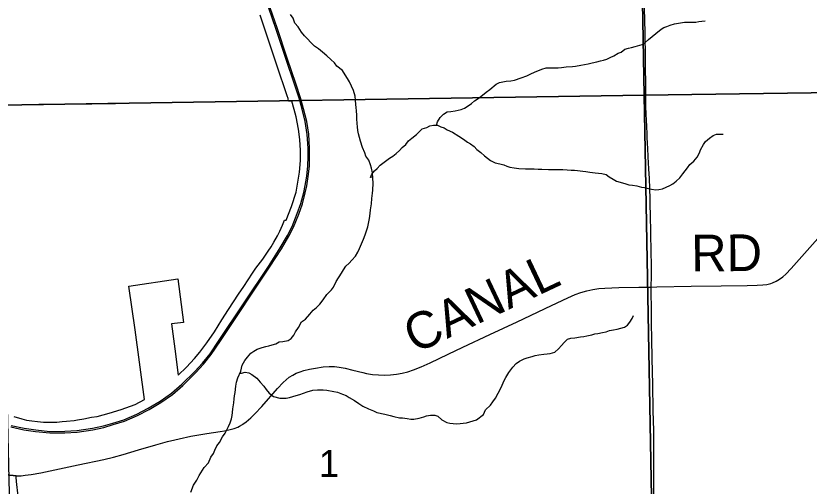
# Model space of a CAD drawing. Extents: x 0 to 34, y 0 to 22.
# Drawn here: x 22.282 to 23.511, y 14.057 to 14.786 of the extents above; entities that cross this region are included whole.
import ezdxf

# ---------------------------------------------------------------- set-up
doc = ezdxf.new("R2010")
doc.units = 0
for name, color, linetype in [('GM_X_City_Street', 7, 'Continuous'), ('GM_X_Corporation', 7, 'Continuous'), ('GM_X_County_Road', 7, 'Continuous'), ('GM_X_County_Road_Text', 7, 'Continuous'), ('GM_X_Minor_River', 7, 'Continuous'), ('GM_X_Rail_Line', 7, 'Continuous'), ('GM_X_Section', 7, 'Continuous'), ('GM_X_Section_Text', 7, 'Continuous'), ('GM_X_Township_Road', 7, 'Continuous')]:
    doc.layers.add(name, color=color, linetype=linetype)

msp = doc.modelspace()

# ---------------------------------------------------------------- linework, layer by layer
at = {"layer": 'GM_X_City_Street'}
msp.add_lwpolyline([(22.26, 14.6472), (22.2903, 14.648), (22.3156, 14.6486), (22.3178, 14.6487), (22.3997, 14.6493), (22.4366, 14.65)], dxfattribs=at)
at = {"layer": 'GM_X_Corporation'}
msp.add_lwpolyline([(22.2788, 14.1648), (22.2916, 14.1611), (22.2988, 14.1594), (22.3071, 14.1583), (22.3156, 14.1571), (22.3251, 14.1564), (22.3363, 14.1562), (22.3456, 14.1563), (22.354, 14.1571), (22.3606, 14.1578), (22.3724, 14.159), (22.3774, 14.1598), (22.3876, 14.1611), (22.3992, 14.1637), (22.4082, 14.1649), (22.4268, 14.17), (22.4452, 14.1759), (22.4667, 14.1836), (22.4815, 14.1915), (22.467, 14.2995), (22.4571, 14.3667), (22.5328, 14.3785), (22.5418, 14.3104), (22.5231, 14.3083), (22.5283, 14.27), (22.5338, 14.2291), (22.5467, 14.2416), (22.5587, 14.2547), (22.5672, 14.2647), (22.5777, 14.2791), (22.5897, 14.2964), (22.6011, 14.3147), (22.6115, 14.3309), (22.6269, 14.3543), (22.6353, 14.3665), (22.6489, 14.3869), (22.6537, 14.3946), (22.6649, 14.409), (22.6732, 14.4212), (22.6775, 14.4277), (22.6819, 14.4351), (22.6873, 14.4449), (22.6911, 14.4523), (22.6952, 14.4614), (22.6983, 14.4691), (22.7006, 14.4691), (22.7091, 14.4902), (22.7161, 14.5127), (22.7215, 14.5438), (22.7229, 14.5617), (22.7229, 14.5771), (22.7219, 14.5941), (22.7199, 14.61), (22.7161, 14.6295), (22.7133, 14.6409), (22.7096, 14.6537), (22.7046, 14.6538), (22.704, 14.6577), (22.7025, 14.6618), (22.6865, 14.7092), (22.6603, 14.7871)], dxfattribs=at)
at = {"layer": 'GM_X_County_Road'}
for points in [[(23.2664, 14.3656), (23.275, 14.3658), (23.3279, 14.367), (23.3744, 14.3676), (23.4147, 14.3681), (23.4302, 14.3683), (23.4394, 14.3689), (23.4455, 14.3697), (23.4514, 14.3711), (23.4543, 14.3721), (23.4599, 14.3745), (23.4652, 14.3776), (23.4702, 14.3812), (23.4747, 14.3853), (23.4831, 14.3943), (23.5283, 14.4456)], [(22.6331, 14.1526), (22.6339, 14.1531), (22.6389, 14.1567), (22.6459, 14.1628), (22.6524, 14.1693), (22.6629, 14.1807), (22.6875, 14.2086), (22.696, 14.2177), (22.7006, 14.2219), (22.7056, 14.2258), (22.7109, 14.2291), (22.7165, 14.232), (22.7223, 14.2343), (22.7283, 14.2362), (22.7372, 14.2383), (22.7461, 14.2401), (22.7582, 14.2417), (22.7675, 14.2424), (22.7758, 14.2423), (22.783, 14.2415), (22.7921, 14.2397), (22.8043, 14.2366), (22.8194, 14.2329), (22.8254, 14.2316), (22.8346, 14.2302), (22.8438, 14.2293), (22.853, 14.229), (22.8623, 14.2294), (22.8715, 14.2303), (22.8806, 14.2319), (22.8895, 14.2341), (22.8983, 14.2371), (22.9097, 14.2417), (22.9239, 14.248), (22.9518, 14.2615), (22.9743, 14.2722), (23.0164, 14.292), (23.0586, 14.3117), (23.112, 14.3369), (23.1372, 14.3489), (23.1487, 14.3538), (23.1575, 14.357), (23.1665, 14.3597), (23.1756, 14.3617), (23.1849, 14.3631), (23.1942, 14.3639), (23.216, 14.3647), (23.247, 14.3654), (23.2664, 14.3656)], [(22.5984, 14.1418), (22.6053, 14.1429), (22.6143, 14.1448), (22.6203, 14.1464), (22.626, 14.1486), (22.6287, 14.1499), (22.6331, 14.1526)], [(22.5282, 14.129), (22.5349, 14.1306), (22.5532, 14.1343), (22.5777, 14.1385), (22.5984, 14.1418)], [(22.2824, 14.0728), (22.2904, 14.0732), (22.2966, 14.0739), (22.3058, 14.0752), (22.321, 14.0779), (22.3788, 14.0899), (22.4183, 14.0984), (22.4334, 14.1019), (22.4484, 14.1059), (22.472, 14.1131), (22.4988, 14.1213), (22.5168, 14.1262), (22.5282, 14.129)], [(22.2159, 14.0893), (22.2266, 14.0863), (22.2358, 14.0837), (22.2507, 14.0795), (22.2629, 14.0764), (22.2719, 14.0743), (22.2778, 14.0733), (22.2824, 14.0728)]]:
    msp.add_lwpolyline(points, dxfattribs=at)
at = {"layer": 'GM_X_Minor_River'}
for points in [[(22.8027, 14.407), (22.8083, 14.4132), (22.812, 14.4197), (22.8146, 14.4254), (22.8205, 14.4399), (22.8231, 14.4464), (22.8257, 14.4544), (22.8275, 14.459), (22.8282, 14.464), (22.83, 14.4716), (22.831, 14.4796), (22.8317, 14.4853), (22.8331, 14.4944), (22.8334, 14.5028), (22.8344, 14.5111), (22.8351, 14.5157), (22.8358, 14.5263), (22.8353, 14.5343), (22.8344, 14.5427), (22.8332, 14.5499), (22.8312, 14.5548), (22.8288, 14.562), (22.8242, 14.5684), (22.8226, 14.5737), (22.8191, 14.582), (22.8159, 14.5914), (22.8131, 14.6032), (22.8119, 14.6081), (22.8111, 14.6138), (22.811, 14.6191), (22.8105, 14.6263), (22.8101, 14.632), (22.8096, 14.6384), (22.8092, 14.6437), (22.8087, 14.6483), (22.8082, 14.6551), (22.8078, 14.6612), (22.805, 14.6699), (22.7991, 14.6835), (22.796, 14.6888), (22.7921, 14.6944), (22.7879, 14.7012), (22.7794, 14.7079), (22.7755, 14.7128), (22.7698, 14.7184), (22.7636, 14.7237), (22.7571, 14.7293), (22.7509, 14.7345), (22.7448, 14.739), (22.7398, 14.7439), (22.7336, 14.7506), (22.729, 14.7547), (22.7247, 14.7604), (22.7193, 14.769), (22.7143, 14.7743), (22.7115, 14.7822), (22.7073, 14.7879)], [(22.9339, 14.6165), (22.9353, 14.6215), (22.9394, 14.6284), (22.9443, 14.6334), (22.95, 14.6369), (22.9557, 14.6377), (22.9625, 14.6386), (22.9674, 14.6394), (22.972, 14.6406), (22.9773, 14.6426), (22.9829, 14.6464), (22.9878, 14.6499), (22.9927, 14.6542), (22.998, 14.6577), (23.0048, 14.6627), (23.0104, 14.6673), (23.0161, 14.6719), (23.0262, 14.6801), (23.0315, 14.6824), (23.0364, 14.6836), (23.0418, 14.6844), (23.049, 14.6853), (23.0547, 14.6861), (23.0649, 14.6897), (23.0736, 14.6928), (23.08, 14.696), (23.0857, 14.6983), (23.0967, 14.7034), (23.1035, 14.705), (23.1088, 14.7055), (23.1141, 14.7055), (23.1221, 14.7053), (23.1274, 14.7057), (23.1347, 14.7066), (23.1442, 14.7075), (23.1491, 14.7079), (23.1574, 14.7095), (23.1684, 14.7116), (23.1749, 14.7128), (23.1821, 14.7144), (23.1878, 14.716), (23.1923, 14.7172), (23.1973, 14.7188), (23.2025, 14.7212), (23.2082, 14.7239), (23.215, 14.7278), (23.2196, 14.7297), (23.2256, 14.734), (23.2313, 14.7356), (23.2358, 14.7368), (23.2415, 14.7384), (23.2521, 14.7416), (23.257, 14.7443), (23.2619, 14.7489), (23.2679, 14.7539), (23.2732, 14.7582), (23.2815, 14.7651), (23.286, 14.7678), (23.2905, 14.7694), (23.2955, 14.7714), (23.3023, 14.7734), (23.3114, 14.775), (23.3178, 14.7759), (23.3353, 14.7761), (23.3399, 14.7769), (23.3448, 14.7774), (23.3498, 14.7782)], [(22.8351, 14.5358), (22.8315, 14.5354), (22.8337, 14.5404), (22.8374, 14.5454), (22.8419, 14.5492), (22.8464, 14.5542), (22.8525, 14.5589), (22.8611, 14.5651), (22.866, 14.5682), (22.8713, 14.5724), (22.8762, 14.577), (22.8807, 14.5816), (22.8863, 14.5867), (22.8901, 14.592), (22.8957, 14.5963), (22.9025, 14.6017), (22.907, 14.6059), (22.9115, 14.6105), (22.9187, 14.6129), (22.9236, 14.6156), (22.9289, 14.6165), (22.935, 14.6166), (22.9404, 14.614), (22.9453, 14.6121), (22.9503, 14.6092), (22.9584, 14.6055), (22.9683, 14.5995), (22.9756, 14.5947), (22.9818, 14.5902), (22.9863, 14.5876), (22.9921, 14.5831), (22.9964, 14.5786), (23.0025, 14.5738), (23.0079, 14.5689), (23.0125, 14.5652), (23.0171, 14.5618), (23.0248, 14.5581), (23.032, 14.5567), (23.0381, 14.5549), (23.0427, 14.5527), (23.0473, 14.5512), (23.0542, 14.5501), (23.0614, 14.5495), (23.0717, 14.5489), (23.0781, 14.5489), (23.085, 14.5487), (23.0911, 14.5484), (23.0968, 14.5481), (23.1074, 14.5478), (23.1128, 14.5479), (23.1204, 14.5476), (23.1295, 14.5477), (23.1363, 14.5471), (23.1421, 14.5468), (23.1474, 14.5465), (23.1519, 14.5461), (23.1603, 14.5451), (23.1649, 14.5444), (23.1714, 14.5434), (23.1794, 14.5423), (23.1847, 14.542), (23.19, 14.5413), (23.1965, 14.5399), (23.2011, 14.5365), (23.2073, 14.5328), (23.2126, 14.5298), (23.2252, 14.5258), (23.2317, 14.524), (23.2371, 14.5233), (23.2439, 14.5223), (23.2512, 14.5205), (23.2561, 14.5198), (23.2618, 14.5183), (23.2668, 14.5173), (23.2733, 14.5162), (23.2782, 14.5167), (23.2835, 14.5179), (23.2949, 14.523), (23.2998, 14.5257), (23.3051, 14.5296), (23.3107, 14.5346), (23.3152, 14.5411), (23.3223, 14.5503), (23.326, 14.5553), (23.3324, 14.5607), (23.3373, 14.5668), (23.341, 14.5737), (23.3428, 14.5783), (23.3473, 14.5867), (23.3503, 14.5913), (23.3563, 14.5963), (23.362, 14.6002), (23.3673, 14.6022), (23.3726, 14.6026), (23.3775, 14.6027)], [(22.5533, 14.0478), (22.5573, 14.0585), (22.5626, 14.0661), (22.5659, 14.0734), (22.5737, 14.086), (22.5805, 14.0934), (22.5842, 14.1021), (22.5883, 14.1075), (22.5905, 14.1129), (22.5934, 14.1194), (22.5976, 14.1247), (22.6024, 14.1335), (22.6065, 14.1393), (22.6113, 14.1492), (22.6139, 14.155), (22.6161, 14.1611), (22.6172, 14.1664), (22.6179, 14.1713), (22.6182, 14.177), (22.6196, 14.1862), (22.6203, 14.1923), (22.621, 14.1968), (22.6217, 14.2022), (22.6227, 14.2117), (22.6241, 14.2181), (22.6259, 14.225), (22.6304, 14.2353), (22.6329, 14.2445), (22.6366, 14.2517), (22.6407, 14.2567), (22.646, 14.2629), (22.6509, 14.2664), (22.6558, 14.2691), (22.6637, 14.2718), (22.6694, 14.2734), (22.674, 14.2746), (22.6789, 14.2762), (22.6846, 14.2778), (22.6899, 14.2806), (22.6959, 14.2814), (22.7039, 14.2826), (22.7088, 14.2857), (22.7129, 14.2911), (22.7151, 14.2961), (22.72, 14.303), (22.7248, 14.3114), (22.7309, 14.316), (22.7376, 14.3233), (22.7425, 14.3299), (22.7477, 14.3341), (22.753, 14.3391), (22.7579, 14.3456), (22.7638, 14.3541), (22.771, 14.361), (22.774, 14.3656), (22.7784, 14.3744), (22.7866, 14.3871), (22.7896, 14.3924), (22.7933, 14.3978), (22.7982, 14.4028), (22.8027, 14.407)], [(23.2296, 14.3063), (23.2333, 14.3113), (23.2367, 14.3167), (23.2389, 14.3217)], [(22.629, 14.2323), (22.6319, 14.2323), (22.6372, 14.2339), (22.6429, 14.2324), (22.6475, 14.2302), (22.6556, 14.2243), (22.6606, 14.2182), (22.666, 14.2122), (22.6699, 14.2066), (22.6745, 14.2013), (22.6811, 14.1961), (22.691, 14.1932), (22.7009, 14.1933), (22.7058, 14.1945), (22.7111, 14.1958), (22.7164, 14.1973), (22.7221, 14.1989), (22.7278, 14.2013), (22.7331, 14.2033), (22.7422, 14.2057), (22.7494, 14.2065), (22.7581, 14.2063), (22.7639, 14.2059), (22.7745, 14.2038), (22.7802, 14.2027), (22.7883, 14.1998), (22.7936, 14.1976), (22.7986, 14.1946), (22.8067, 14.1898), (22.8136, 14.1853), (22.8197, 14.1812), (22.8281, 14.1768), (22.8362, 14.1735), (22.8411, 14.1713), (22.8537, 14.1688), (22.8617, 14.1666), (22.8674, 14.1652), (22.8762, 14.163), (22.8808, 14.1627), (22.8884, 14.1616), (22.8937, 14.161), (22.8987, 14.161), (22.9067, 14.1623), (22.9139, 14.1643), (22.9184, 14.1662), (22.9245, 14.1671), (22.9309, 14.1668), (22.9355, 14.1653), (22.9421, 14.1597), (22.9497, 14.1556), (22.9543, 14.1545), (22.9596, 14.1542), (22.965, 14.1536), (22.9703, 14.154), (22.9748, 14.1544), (22.9802, 14.1553), (22.9855, 14.1565), (22.9957, 14.1597), (23.0066, 14.1682), (23.0096, 14.1754), (23.0175, 14.1827), (23.0208, 14.1877), (23.0249, 14.1935), (23.0294, 14.2011), (23.0327, 14.2076), (23.0353, 14.2137), (23.0383, 14.2206), (23.0409, 14.2252), (23.0457, 14.2329), (23.0521, 14.2413), (23.0573, 14.2471), (23.0622, 14.2506), (23.0694, 14.2541), (23.0739, 14.2557), (23.0819, 14.258), (23.0864, 14.2596), (23.0921, 14.2605), (23.0997, 14.2613), (23.105, 14.2621), (23.11, 14.2626), (23.1168, 14.2646), (23.1228, 14.2696), (23.1273, 14.275), (23.1314, 14.2796), (23.1367, 14.285), (23.142, 14.2862), (23.1481, 14.287), (23.1568, 14.2883), (23.1617, 14.2891), (23.1663, 14.2899), (23.1743, 14.2916), (23.1788, 14.2928), (23.1834, 14.2936), (23.1906, 14.2952), (23.1963, 14.2964), (23.2019, 14.298), (23.208, 14.2992), (23.2137, 14.3004), (23.2194, 14.302), (23.2247, 14.3036), (23.2296, 14.3063)]]:
    msp.add_lwpolyline(points, dxfattribs=at)
at = {"layer": 'GM_X_Rail_Line'}
for points in [[(22.2742, 14.1489), (22.2944, 14.1444), (22.3126, 14.1418), (22.3347, 14.1396), (22.358, 14.1397), (22.377, 14.1409), (22.4013, 14.1444), (22.4184, 14.148), (22.4328, 14.1523), (22.4503, 14.1578), (22.4704, 14.1665), (22.4884, 14.1758), (22.5068, 14.1866), (22.5248, 14.1991), (22.541, 14.213), (22.5611, 14.2329), (22.5729, 14.2461), (22.5848, 14.2608), (22.5993, 14.282), (22.6752, 14.3963), (22.6937, 14.425), (22.7051, 14.4443), (22.7121, 14.4586), (22.7203, 14.4786), (22.7259, 14.4945), (22.7304, 14.5116), (22.7327, 14.5224), (22.7351, 14.5371), (22.7368, 14.553), (22.7372, 14.5673), (22.7371, 14.5809), (22.7357, 14.6023), (22.7326, 14.6223), (22.7278, 14.6417), (22.723, 14.6588), (22.7163, 14.6794), (22.7024, 14.7204), (22.6869, 14.7671), (22.6763, 14.7984)], [(22.2748, 14.1512), (22.2948, 14.1467), (22.3129, 14.1441), (22.3348, 14.1419), (22.3579, 14.1421), (22.3767, 14.1433), (22.4009, 14.1467), (22.4178, 14.1503), (22.4321, 14.1546), (22.4494, 14.16), (22.4694, 14.1686), (22.4872, 14.1778), (22.5055, 14.1886), (22.5233, 14.2009), (22.5394, 14.2148), (22.5594, 14.2345), (22.5711, 14.2477), (22.5829, 14.2622), (22.5973, 14.2833), (22.6733, 14.3976), (22.6917, 14.4262), (22.703, 14.4454), (22.71, 14.4596), (22.7181, 14.4795), (22.7237, 14.4951), (22.7281, 14.5121), (22.7304, 14.5229), (22.7327, 14.5374), (22.7345, 14.5532), (22.7348, 14.5673), (22.7347, 14.5808), (22.7333, 14.6021), (22.7303, 14.6219), (22.7255, 14.6411), (22.7208, 14.6581), (22.7141, 14.6786), (22.7002, 14.7196), (22.6847, 14.7664), (22.6741, 14.7976)]]:
    msp.add_lwpolyline(points, dxfattribs=at)
at = {"layer": 'GM_X_Section'}
for points in [[(23.2375, 15.6726), (24.0823, 15.695), (24.1117, 14.6757), (23.9946, 14.6733), (23.2551, 14.663)], [(23.2375, 15.6726), (23.2551, 14.663), (22.2584, 14.6473), (22.2313, 15.6515)], [(23.2551, 14.663), (23.9946, 14.6733), (23.9771, 14.1383), (23.9802, 13.6328), (23.2745, 13.6253), (23.274, 13.6432)], [(22.2584, 14.6473), (23.2551, 14.663), (23.274, 13.6432), (22.2822, 13.6222)]]:
    msp.add_lwpolyline(points, close=True, dxfattribs=at)
at = {"layer": 'GM_X_Township_Road'}
for points in [[(23.2578, 14.661), (23.2577, 14.6753), (23.2577, 14.687), (23.2576, 14.6991), (23.2576, 14.709), (23.2574, 14.7238), (23.2572, 14.7335), (23.2571, 14.7454), (23.2569, 14.755), (23.2568, 14.7619), (23.2564, 14.7773), (23.2559, 14.7993)], [(23.2664, 14.3656), (23.2664, 14.3693), (23.2665, 14.3786), (23.2665, 14.3972), (23.2657, 14.4468), (23.2655, 14.459), (23.2651, 14.4683), (23.2649, 14.4797), (23.2647, 14.4906), (23.2645, 14.502), (23.2642, 14.5182), (23.2637, 14.5337), (23.2628, 14.5486), (23.2617, 14.5671), (23.2608, 14.581), (23.2603, 14.5882), (23.26, 14.5977), (23.2598, 14.6039), (23.2593, 14.6132), (23.2587, 14.6255), (23.2585, 14.6317), (23.258, 14.6472), (23.2578, 14.661)], [(23.2725, 13.8889), (23.2724, 13.8982), (23.2722, 13.9185), (23.272, 13.9337), (23.2718, 13.9537), (23.2715, 13.9756), (23.2708, 14.0096), (23.2702, 14.05), (23.2704, 14.0561), (23.2702, 14.0686), (23.2702, 14.0779), (23.2701, 14.0965), (23.2701, 14.1429), (23.2694, 14.174), (23.2686, 14.2143), (23.2679, 14.2546), (23.2672, 14.2855), (23.2668, 14.309), (23.2665, 14.3321), (23.2662, 14.3569), (23.2664, 14.3656)], [(22.2824, 14.0728), (22.2778, 14.0733), (22.2719, 14.0743), (22.2629, 14.0764), (22.2507, 14.0795), (22.2358, 14.0837), (22.2266, 14.0863), (22.2159, 14.0893)], [(22.2857, 14.0414), (22.2833, 14.064), (22.2827, 14.0708), (22.2824, 14.0728)]]:
    msp.add_lwpolyline(points, dxfattribs=at)

# ---------------------------------------------------------------- texts
at = {"layer": 'GM_X_County_Road_Text'}
for s, rotation, p in [('RD', 0.494, (23.3284, 14.3896)), ('CANAL', 25.3274, (22.9004, 14.2617))]:
    msp.add_text(s, height=0.05682, rotation=rotation, dxfattribs=at).set_placement(p)
at = {"layer": 'GM_X_Section_Text'}
msp.add_text('1', height=0.0419, rotation=0, dxfattribs=at).set_placement((22.7516, 14.0711))

doc.saveas('drawing.dxf')
